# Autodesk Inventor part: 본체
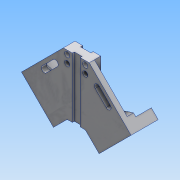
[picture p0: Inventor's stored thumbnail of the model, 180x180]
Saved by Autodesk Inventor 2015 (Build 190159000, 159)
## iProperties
Created: 2019-04
Part Number: 본체
Material: 알루미늄 6061
Document SubType Name: Modeling
Designer: SCD-A01
Density: 2.7 g/cm^3
Appearance: 알루미늄 - 평지
Mass: 601.509 g
Surface Area: 426.536 cm^2
Volume: 222.781 cm^3
Author: SCD-A01
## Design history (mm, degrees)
sketch "스케치1"
  geometry: L1 (84.853, 0)-(0, 84.853); L2 (0, 84.853)-(-84.853, 0); L3 (-84.853, 0)-(0, -84.853); L4 (0, -84.853)-(84.853, 0); L5 (84.853, 0)-(-84.853, 0); L6 (0, -84.853)-(0, 84.853); L7 (100, 0)-(-100, 0); 4 further points
  constraints: 14 end point, 3 midpoint, 2 coincident, 2 perpendicular, 1 horizontal, 1 point on line
  dimensions: "d2" = 120 distance of L1.start L1.end; "d3" = 120 distance of L1.end L2.end; "d4" = 120 distance of L2.end L3.end; "d5" = 200 distance of L7.start L7.end
extrude "돌출1" new body sketch "스케치1" distance "d6" = 42; taper "d7" = 0 deg
sketch "스케치2"
  geometry: L1 (-84.853, 0)-(0, -84.853) reference; L2 (-20, -64.853)-(20, -64.853); L3 (-20, -64.853)-(0, -84.853); L4 (20, -64.853)-(0, -84.853); 1 further point
  constraints: 6 end point, 1 horizontal, 1 point on line
  dimensions: "d8" = 40 distance of L2.start L2.end; "d9" = 20 distance from line of L1.end L2
extrude "돌출2" cut sketch "스케치2" distance "d10" = 42; taper "d11" = 0 deg
sketch "스케치3"
  geometry: L1 (-20, -64.853)-(20, -64.853) reference; L2 (0, -64.853)-(0, 28.147); L3 (-84.853, 0)-(0, 84.853); L4 (84.853, 0)-(0, 84.853) reference; L5 (-14.005, 28.147)-(14.005, 28.147); L6 (-14.005, 28.147)-(-35.355, 49.497); L7 (14.005, 28.147)-(35.355, 49.497); L8 (-35.355, 49.497)-(0, 84.853); L9 (0, 84.853)-(35.355, 49.497); 1 further point
  constraints: 14 end point, 2 midpoint, 1 collinear, 1 horizontal, 1 parallel, 1 perpendicular, 1 vertical
  dimensions: "d12" = 93 distance of L2.end L2.start; "d22" = 50 distance between parallel lines of L3 L7; "d23" = 50 distance between parallel lines of L4 L6
extrude "돌출3" cut sketch "스케치3" distance "d24" = 42; taper "d25" = 0 deg
sketch "스케치4"
  geometry: L1 (-35.355, 49.497)-(-84.853, 0) reference; L2 (84.853, 0)-(35.355, 49.497) reference; L3 (-24.749, 38.891)-(-74.246, -10.607); L4 (74.246, -10.607)-(24.749, 38.891); L5 (-74.246, -10.607)-(0, -84.853); L6 (0, -84.853)-(74.246, -10.607); L7 (-24.749, 38.891)-(24.749, 38.891); 1 further point
  constraints: 10 end point, 2 parallel, 1 horizontal
  dimensions: "d26" = 15 distance between parallel lines of L1 L3; "d27" = 15 distance between parallel lines of L2 L4; "d28" = 49.49747 distance of L3.start L4.end; "d30" = 74.24621 horizontal distance of L3.end L5.end; "d31" = 105 distance of L5.end L4.start; "d32" = 90 deg angle of L6 L5; "d33" = 148.49242 distance of L4.start L3.end
extrude "돌출4" cut sketch "스케치4" distance "d34" = 24; taper "d35" = 0 deg
sketch "스케치5"
  geometry: L1 (40, 18)-(0, 18) reference; L2 (12, 18)-(12, 14.5); L3 (12, 14.5)-(28, 14.5); L4 (28, 14.5)-(28, 18); L5 (28, 18)-(12, 18); 2 further points
  constraints: 8 end point, 3 perpendicular, 2 midpoint, 1 vertical
  dimensions: "d39" = 16 distance between parallel lines of L4 L2; "d40" = 3.5 distance of L2.start L2.end
extrude "돌출5" cut sketch "스케치5" stored distance "d41" = 24; taper "d42" = 0 deg
sketch "스케치6"
  geometry: L1 (40, 0)-(0, 0) reference; L2 (14, 0)-(14, 3); L3 (14, 3)-(26, 3); L4 (26, 3)-(26, 0); L5 (26, 0)-(14, 0); 2 further points
  constraints: 8 end point, 2 midpoint, 2 perpendicular, 2 vertical
  dimensions: "d43" = 3 distance of L3.end L4.end; "d44" = 12 distance of L2.end L3.end
extrude "돌출6" cut sketch "스케치6" stored distance "d45" = 24; taper "d46" = 0 deg
sketch "스케치7"
  geometry: L1 (-20, -64.853)-(-74.246, -10.607) reference; L2 (-12.649, -58.062)-(-66.895, -3.816); L3 (-35.355, 49.497)-(-84.853, 0) reference; L4 (-21.213, 35.355)-(-70.711, -14.142); L5 (-12.461, 29.965)-(-61.959, -19.532); L6 (-5.438, -51.131)-(-59.684, 3.115); L7 (-70.711, -14.142)-(-49.497, -7.071); L8 (-26.541, 1.743)-(-76.039, -47.754); L9 (-9.571, -15.228)-(-59.068, -64.725); L10 (-20, -64.853)-(-20, -36.569); L11 (-20, -36.569)-(-49.497, -7.071); L12 (-70.711, -14.142)-(-20, -64.853); 1 further point
  constraints: 20 end point, 6 parallel, 3 point on line, 1 perpendicular, 1 vertical
  dimensions: "d47" = 10 distance between parallel lines of L1 L2; "d48" = 20 distance between parallel lines of L3 L4; "d49" = 30 distance between parallel lines of L3 L5; "d50" = 20 distance between parallel lines of L1 L6; "d51" = 40 distance between parallel lines of L3 L8; "d52" = 24 distance between parallel lines of L8 L9; "d54" = 21.2132 horizontal distance of L4.end L7.end
extrude "돌출7" cut sketch "스케치7" distance "d55" = 10; taper "d56" = 0 deg
sketch "스케치8"
  geometry: L1 (-7.071, 21.213)-(-56.569, -28.284); L2 (9.899, 4.243)-(-39.598, -45.255); L3 (-84.853, 0)-(-20, -64.853) reference; L4 (-77.782, 7.071)-(-12.929, -57.782); L5 (-35.355, 49.497)-(-84.853, 0) reference; L6 (-49.497, -21.213)-(-32.527, -38.184); L7 (-52.679, -24.395)-(-35.709, -41.366); L8 (-29.345, -35.002)-(-46.315, -18.031); A1 r 4.5 centre (-49.497, -21.213) between (-46.315, -18.031) and (-52.679, -24.395); A2 r 4.5 centre (-32.527, -38.184) between (-35.709, -41.366) and (-29.345, -35.002); 2 further points
  constraints: 14 end point, 4 point on circle, 4 point on line, 4 tangent, 3 parallel, 2 centre point, 1 midpoint
  dimensions: "d58" = 24 distance between parallel lines of L1 L2; "d59" = 10 distance between parallel lines of L3 L4; "d60" = 40 distance between parallel lines of L1 L5; "d61" = 9 diameter of A2
extrude "돌출8" cut sketch "스케치8" distance "d62" = 10; taper "d63" = 0 deg
sketch "스케치9"
  geometry: L1 (20, -64.853)-(8, -64.853) reference; L2 (0, 0)-(0, -70); L3 (20, -58.853)-(8, -58.853); L4 (14, 0)-(14, -70); C1 r 2.25 at (14, -58.853)
  constraints: 6 end point, 2 parallel, 1 centre point, 1 midpoint, 1 point on line, 1 vertical
  dimensions: "d64" = 70 distance of L2.start L2.end; "d65" = 6 distance between parallel lines of L1 L3; "d66" = 14 distance between parallel lines of L2 L4; "d67" = 4.5 diameter of C1
extrude "돌출9" cut sketch "스케치9" distance "d68" = 8; taper "d69" = 0 deg
sketch "스케치10"
  geometry: C1 r 2.25 at (14, 58.853) reference; C2 r 4 at (14, 58.853); 1 further point
  constraints: 1 centre point, 1 coincident
  dimensions: "d70" = 8 diameter of C2
extrude "돌출10" cut sketch "스케치10" distance "d71" = 10; taper "d72" = 0 deg
sketch "스케치11"
  geometry: L1 (0, 0)-(0, 72.803); C1 r 4 at (14, 58.853) reference; C2 r 4 at (14, 46.853)
  constraints: 2 end point, 1 centre point, 1 vertical
  dimensions: "d73" = 8 diameter of C2; "d74" = 12 distance of C2.centre C1.centre; "d75" = 14 distance from line of C2.centre L1
extrude "돌출11" cut sketch "스케치11" distance "d76" = 10; taper "d77" = 0 deg
sketch "스케치12"
  geometry: C1 r 4 at (14, -46.853) reference; C2 r 2.25 at (14, -46.853); 1 further point
  constraints: 1 centre point, 1 coincident
  dimensions: "d78" = 4.5 diameter of C2
extrude "돌출12" cut sketch "스케치12" distance "d79" = 10; taper "d80" = 0 deg
fillet "모깎기1" dims "d81" = 5
sketch "스케치13"
  geometry: L1 (-24.749, 38.891)-(-35.355, 49.497) reference; L2 (-35.355, 49.497)-(-84.853, 0) reference; 2 further points
  constraints: 1 other
  dimensions: "d84" = 7.5 distance from line of L2 point (-54.801, 19.445); "d85" = 35 distance from line of L1 point (-54.801, 19.445)
feature "엠보싱1" sketch "스케치13" dims "d2" = 120, "d3" = 120, "d4" = 120, "d5" = 200, "d86" = 0.5, "d87" = 0
node "솔리드1"
mirror "대칭1"
mirror "대칭2"
mirror "대칭3"
